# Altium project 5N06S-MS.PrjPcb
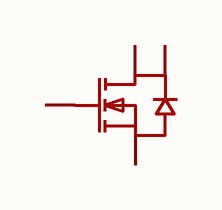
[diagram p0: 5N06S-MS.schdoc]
1 sheet, 1 parts. Net scope: global (net labels, ports and power ports of the same name join across sheets).

## Sheet 5N06S-MS.schdoc
size 127 x 101 mm

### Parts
Q?  5n06s-ms  [SOT-223-4_L6.5-W3.5-P2.30-LS7.0-BR]  (value not drawn)

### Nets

Not connected (* = marked no-connect by the designer): Q? 1(G) 2(D) 3(S) 4(D)

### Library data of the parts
Q? = 5n06s-ms: 数量:1个N沟道;漏源电压(Vdss):60V;连续漏极电流(Id):5A;导通电阻(RDS(on)):80mΩ@10V;耗散功率(Pd):1.5W;阈值电压(Vgs(th)):1.4V;; Manufacturer: MSKSEMI(美森科); AddInBom: yes; ModelId: 925194bf9823436183a3e0b978a8d076; ModelName: SOT-223-4P_L6.5-W3.5-H1.6-LS7.0-P2.30; ModelTransform: 279.89794,255.905,0,180,0,0,-0.0005,-0.0005,0; Number: 1个N沟道; Drain to Source Voltage: 60V; Current - Continuous Drain(Id): 5A; Pd - Power Dissipation: 1.5W; Gate Threshold Voltage (Vgs(th)): 1.4V; Gate Charge(Qg): 9nC@10V; Input Capacitance(Ciss): 350pF; Reverse Transfer Capacitance (Crss@Vds): 23pF; Type: N沟道; Output Capacitance(Coss): 29pF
